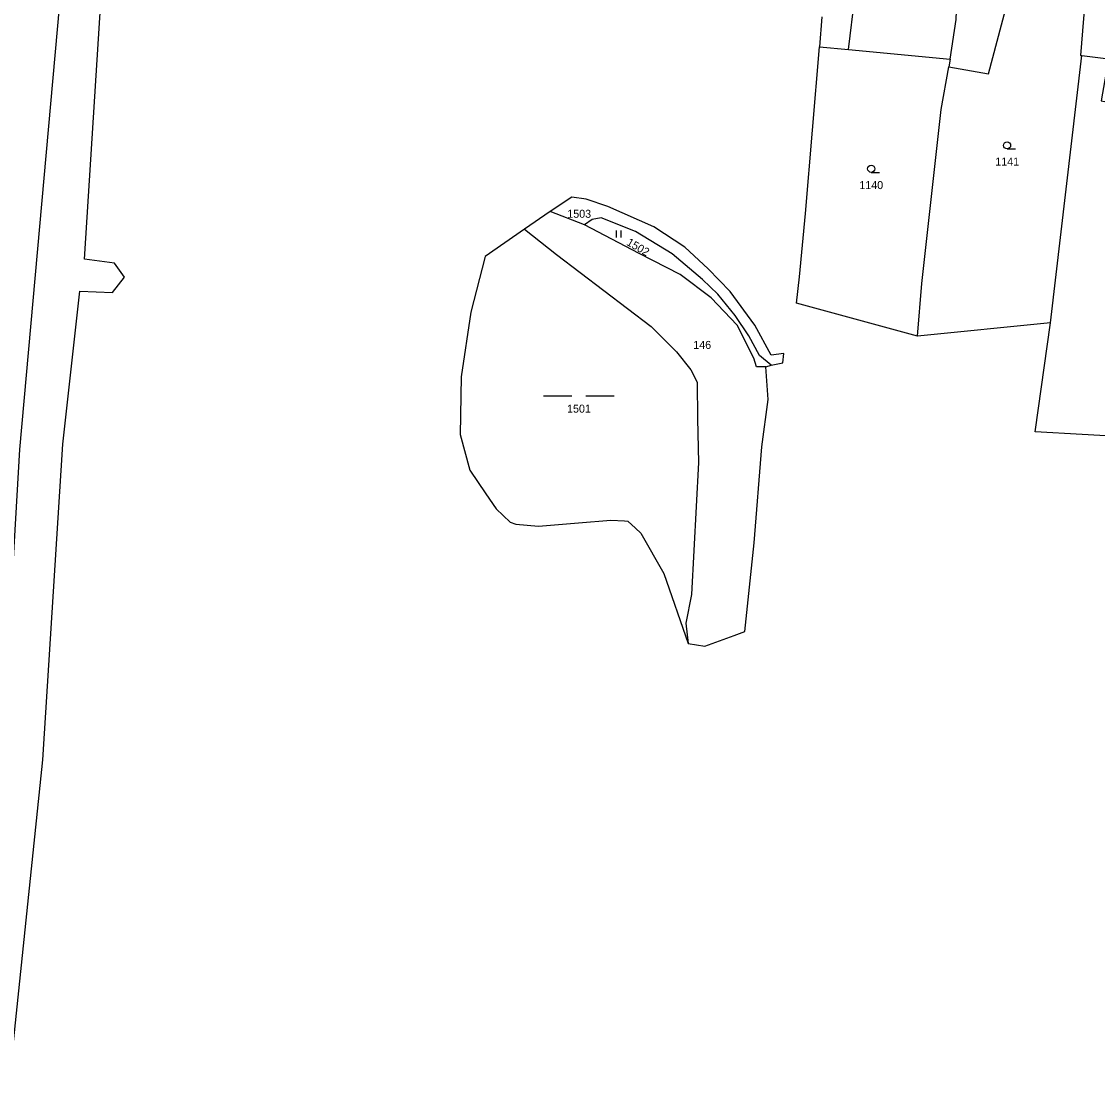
# Model space of a CAD drawing. Extents: x -746176 to -739709, y -1127410 to -1124482.
# Drawn here: x -742472.1 to -742243.5, y -1126433.2 to -1126206.3 of the extents above; entities that cross this region are included whole.
import ezdxf

# ---------------------------------------------------------------- set-up
doc = ezdxf.new("R2010")
doc.units = 0
for name, color, linetype in [('Hranice parcel', 7, 'Continuous'), ('Parcelní čísla', 7, 'Continuous'), ('Vnitřní kresba', 7, 'Continuous'), ('Značky kultur', 7, 'Continuous')]:
    doc.layers.add(name, color=color, linetype=linetype)

msp = doc.modelspace()

# ---------------------------------------------------------------- linework, layer by layer
at = {"layer": 'Hranice parcel'}
for p, q in [((-742302.07, -1126205.33), (-742302.59, -1126211.7)), ((-742274.79, -1126214.34), (-742275.09, -1126215.95)), ((-742253.45, -1126270.36), (-742246.8, -1126213.59)), ((-742359.78, -1126246.7), (-742365.22, -1126250.48)), ((-742352.47, -1126249.57), (-742359.78, -1126246.7)), ((-742253.45, -1126270.36), (-742281.72, -1126273.18)), ((-742313.94, -1126279.73), (-742312.86, -1126279.32))]:
    msp.add_line(p, q, dxfattribs=at)
for points in [[(-742433.87, -1126052.94), (-742447.8, -1126100.68), (-742456.41, -1126109.29), (-742463.16, -1126192.21), (-742472.54, -1126297.27), (-742476.24, -1126360.79), (-742482.39, -1126414.71)], [(-742274.79, -1126214.34), (-742273.54, -1126205.94), (-742273.34, -1126202.32), (-742273.6, -1126202.3), (-742273.12, -1126195.05), (-742269.02, -1126174.69), (-742269.3, -1126174.61), (-742265.06, -1126159.49), (-742261.84, -1126150.05)], [(-742275.09, -1126215.95), (-742266.66, -1126217.47), (-742260.87, -1126195.48), (-742259.76, -1126191.3), (-742252.85, -1126192.83), (-742250.39, -1126193.38), (-742250.2, -1126192.33), (-742246.63, -1126193.07), (-742245.81, -1126193.24)], [(-742245.81, -1126193.24), (-742245.98, -1126199.54), (-742247.06, -1126213.57), (-742246.8, -1126213.59)], [(-742521.95, -1126773.52), (-742504.56, -1126672.68), (-742497, -1126628.23), (-742488.98, -1126567.9), (-742478.35, -1126466.13), (-742467.6, -1126363.23), (-742463.32, -1126296.13), (-742459.73, -1126263.65), (-742452.82, -1126263.88), (-742450.23, -1126260.63), (-742452.38, -1126257.65), (-742458.75, -1126256.81), (-742455.22, -1126201.03)], [(-742281.72, -1126273.18), (-742307.41, -1126266.17), (-742306.81, -1126260.62), (-742305.51, -1126247.12), (-742302.59, -1126211.7)], [(-742302.59, -1126211.7), (-742296.36, -1126212.29), (-742274.79, -1126214.34)], [(-742246.8, -1126213.59), (-742241.16, -1126214.28), (-742242.7, -1126223.21), (-742217.86, -1126227.84)], [(-742281.72, -1126273.18), (-742280.8, -1126262.02), (-742276.72, -1126225.02), (-742275.09, -1126215.95)], [(-742312.86, -1126279.32), (-742310.37, -1126278.83), (-742310.1, -1126276.88), (-742312.85, -1126277.24), (-742316.28, -1126270.87), (-742321.55, -1126263.67), (-742326.18, -1126258.87), (-742331.19, -1126254.3), (-742337.74, -1126249.93), (-742347.56, -1126245.62), (-742352.13, -1126244.1), (-742355.18, -1126243.68), (-742359.78, -1126246.7)], [(-742312.86, -1126279.32), (-742315.34, -1126277.31), (-742317.58, -1126273.13), (-742320.46, -1126268.81), (-742324.19, -1126264.26), (-742327.43, -1126261.18), (-742333.85, -1126255.73), (-742341.65, -1126250.94), (-742348.95, -1126248.05), (-742350.88, -1126248.39), (-742352.47, -1126249.57)], [(-742365.22, -1126250.48), (-742373.57, -1126256.29), (-742376.68, -1126268.07), (-742378.68, -1126281.82), (-742378.89, -1126294.06), (-742376.87, -1126301.65), (-742373.45, -1126306.68), (-742371.27, -1126309.88), (-742368.26, -1126312.68), (-742367.06, -1126313.15), (-742362.27, -1126313.54), (-742353.74, -1126312.85), (-742346.92, -1126312.29), (-742344.01, -1126312.43), (-742343.26, -1126312.47), (-742341.67, -1126313.97), (-742340.52, -1126315.05), (-742335.61, -1126323.62), (-742330.46, -1126338.51)], [(-742365.22, -1126250.48), (-742358.46, -1126255.84), (-742338.35, -1126271.17), (-742332.91, -1126276.5), (-742329.88, -1126280.34), (-742328.57, -1126283), (-742328.5, -1126290.72), (-742328.28, -1126300.04), (-742329.78, -1126328.09), (-742330.94, -1126334.17), (-742330.46, -1126338.51)], [(-742313.94, -1126279.73), (-742315.93, -1126279.73), (-742316.49, -1126277.87), (-742320.07, -1126270.89), (-742325.58, -1126265.02), (-742332.17, -1126260.06), (-742340.89, -1126255.6), (-742352.47, -1126249.57)], [(-742226.78, -1126295.24), (-742256.74, -1126293.53), (-742253.45, -1126270.36)], [(-742330.46, -1126338.51), (-742326.9, -1126339.07), (-742320.68, -1126336.8), (-742318.41, -1126335.97), (-742316.41, -1126317.12), (-742314.83, -1126296.67), (-742313.49, -1126286.65), (-742313.94, -1126279.73)]]:
    msp.add_lwpolyline(points, dxfattribs=at)
at = {"layer": 'Vnitřní kresba'}
msp.add_line((-742296.36, -1126212.29), (-742294.97, -1126200.25), dxfattribs=at)
at = {"layer": 'Značky kultur'}
for p, q in [((-742262.683, -1126233.41), (-742260.933, -1126233.41)), ((-742291.573, -1126238.39), (-742289.823, -1126238.39)), ((-742345.721, -1126252.24), (-742345.721, -1126250.74)), ((-742344.72, -1126252.24), (-742344.72, -1126250.74)), ((-742361.179, -1126285.88), (-742355.179, -1126285.88)), ((-742352.179, -1126285.88), (-742346.179, -1126285.88))]:
    msp.add_line(p, q, dxfattribs=at)
for centre in [(-742262.683, -1126232.66), (-742291.573, -1126237.64)]:
    msp.add_circle(centre, 0.75, dxfattribs=at)

# ---------------------------------------------------------------- texts
at = {"layer": 'Parcelní čísla'}
for s, p in [('1141', (-742265.197, -1126236.96)), ('1140', (-742294.087, -1126241.94)), ('1503', (-742356.147, -1126248.04)), ('146', (-742329.374, -1126275.9)), ('1501', (-742356.197, -1126289.44))]:
    msp.add_text(s, height=1.7, dxfattribs=at).set_placement(p)
msp.add_text('1502', height=1.7, rotation=330, dxfattribs=at).set_placement((-742343.706, -1126253.732))

doc.saveas('drawing.dxf')
